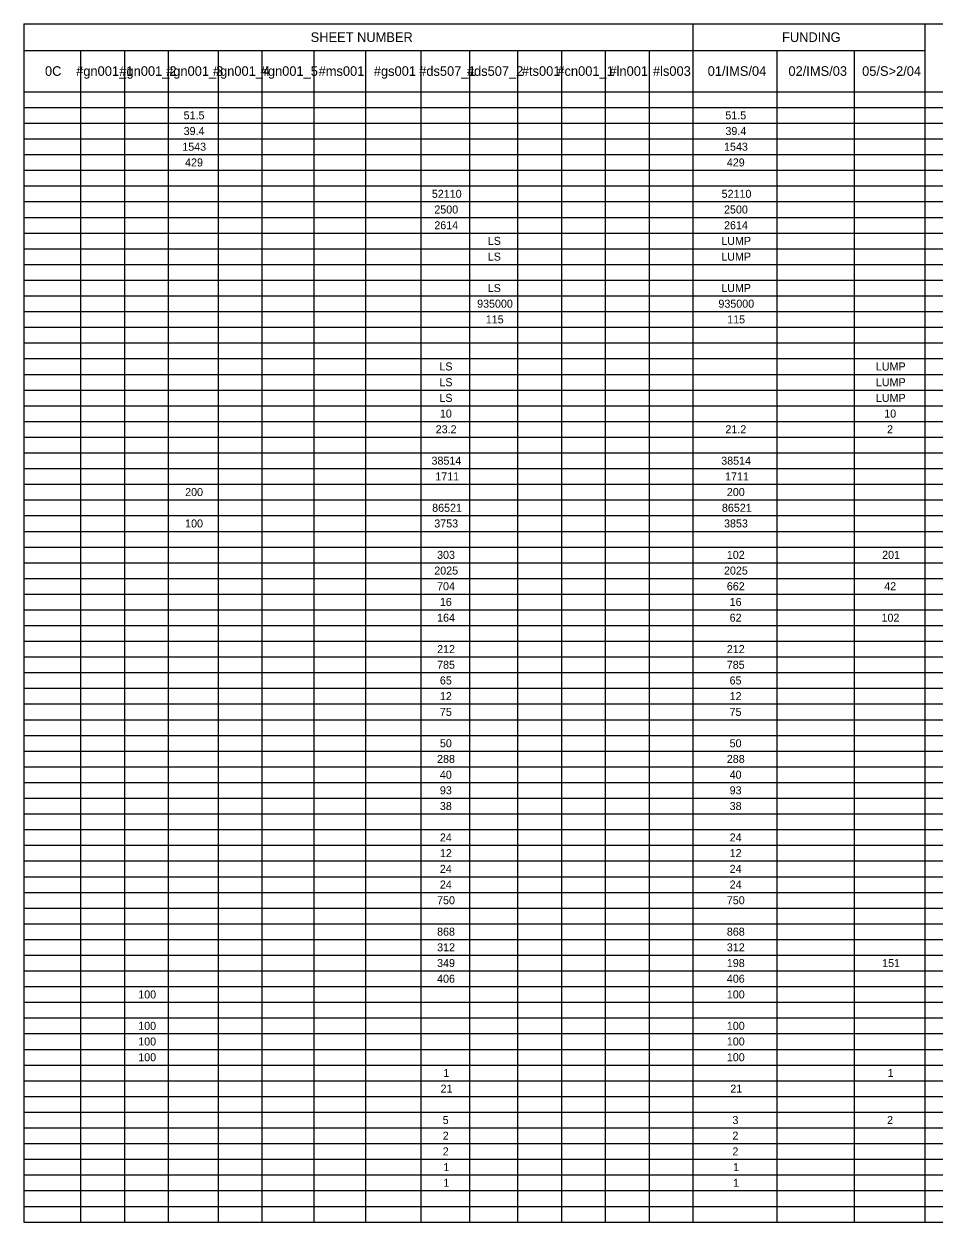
# Model space of a CAD drawing. Extents: x -542 to 295, y -281 to 32.
# Drawn here: x -541.71 to -525.79, y -40.54 to -19.59 of the extents above; entities that cross this region are included whole.
import ezdxf

# ---------------------------------------------------------------- set-up
doc = ezdxf.new("R2010")
doc.units = 0
doc.layers.add('SH_Data', color=7, linetype='Continuous')
doc.layers.add('SH_Text', color=7, linetype='Continuous')

msp = doc.modelspace()

# ---------------------------------------------------------------- linework, layer by layer
at = {"layer": 'SH_Data'}
for p, q in [((-541.706, -19.593), (-511.206, -19.593)), ((-541.706, -19.593), (-541.706, -40.543)), ((-530.01, -19.593), (-530.01, -40.543)), ((-525.956, -19.593), (-525.956, -40.543)), ((-541.706, -20.054), (-525.956, -20.054)), ((-540.716, -20.054), (-540.716, -40.543)), ((-539.95, -20.054), (-539.95, -40.543)), ((-539.184, -20.054), (-539.184, -40.543)), ((-538.311, -20.054), (-538.311, -40.543)), ((-537.545, -20.054), (-537.545, -40.543)), ((-536.64, -20.054), (-536.64, -40.543)), ((-535.736, -20.054), (-535.736, -40.543)), ((-534.767, -20.054), (-534.767, -40.543)), ((-533.916, -20.054), (-533.916, -40.543)), ((-533.075, -20.054), (-533.075, -40.543)), ((-532.309, -20.054), (-532.309, -40.543)), ((-531.543, -20.054), (-531.543, -40.543)), ((-530.776, -20.054), (-530.776, -40.543)), ((-528.542, -20.054), (-528.542, -40.543)), ((-527.19, -20.054), (-527.19, -40.543)), ((-541.706, -20.778), (-511.206, -20.778)), ((-541.706, -21.053), (-511.206, -21.053)), ((-541.706, -21.327), (-511.206, -21.327)), ((-541.706, -21.602), (-511.206, -21.602)), ((-541.706, -21.876), (-511.206, -21.876)), ((-541.706, -22.151), (-511.206, -22.151)), ((-541.706, -22.425), (-511.206, -22.425)), ((-541.706, -22.7), (-511.206, -22.7)), ((-541.706, -22.975), (-511.206, -22.975)), ((-541.706, -23.249), (-511.206, -23.249)), ((-541.706, -23.524), (-511.206, -23.524)), ((-541.706, -23.798), (-511.206, -23.798)), ((-541.706, -24.073), (-511.206, -24.073)), ((-541.706, -24.347), (-511.206, -24.347)), ((-541.706, -24.622), (-511.206, -24.622)), ((-541.706, -24.896), (-511.206, -24.896)), ((-541.706, -25.171), (-511.206, -25.171)), ((-541.706, -25.445), (-511.206, -25.445)), ((-541.706, -25.72), (-511.206, -25.72)), ((-541.706, -25.994), (-511.206, -25.994)), ((-541.706, -26.269), (-511.206, -26.269)), ((-541.706, -26.543), (-511.206, -26.543)), ((-541.706, -26.818), (-511.206, -26.818)), ((-541.706, -27.092), (-511.206, -27.092)), ((-541.706, -27.367), (-511.206, -27.367)), ((-541.706, -27.641), (-511.206, -27.641)), ((-541.706, -27.916), (-511.206, -27.916)), ((-541.706, -28.19), (-511.206, -28.19)), ((-541.706, -28.465), (-511.206, -28.465)), ((-541.706, -28.739), (-511.206, -28.739)), ((-541.706, -29.014), (-511.206, -29.014)), ((-541.706, -29.288), (-511.206, -29.288)), ((-541.706, -29.563), (-511.206, -29.563)), ((-541.706, -29.837), (-511.206, -29.837)), ((-541.706, -30.112), (-511.206, -30.112)), ((-541.706, -30.386), (-511.206, -30.386)), ((-541.706, -30.661), (-511.206, -30.661)), ((-541.706, -30.935), (-511.206, -30.935)), ((-541.706, -31.21), (-511.206, -31.21)), ((-541.706, -31.484), (-511.206, -31.484)), ((-541.706, -31.759), (-511.206, -31.759)), ((-541.706, -32.033), (-511.206, -32.033)), ((-541.706, -32.308), (-511.206, -32.308)), ((-541.706, -32.582), (-511.206, -32.582)), ((-541.706, -32.857), (-511.206, -32.857)), ((-541.706, -33.131), (-511.206, -33.131)), ((-541.706, -33.406), (-511.206, -33.406)), ((-541.706, -33.68), (-511.206, -33.68)), ((-541.706, -33.955), (-511.206, -33.955)), ((-541.706, -34.229), (-511.206, -34.229)), ((-541.706, -34.504), (-511.206, -34.504)), ((-541.706, -34.778), (-511.206, -34.778)), ((-541.706, -35.053), (-511.206, -35.053)), ((-541.706, -35.327), (-511.206, -35.327)), ((-541.706, -35.602), (-511.206, -35.602)), ((-541.706, -35.876), (-511.206, -35.876)), ((-541.706, -36.151), (-511.206, -36.151)), ((-541.706, -36.425), (-511.206, -36.425)), ((-541.706, -36.7), (-511.206, -36.7)), ((-541.706, -36.975), (-511.206, -36.975)), ((-541.706, -37.249), (-511.206, -37.249)), ((-541.706, -37.524), (-511.206, -37.524)), ((-541.706, -37.798), (-511.206, -37.798)), ((-541.706, -38.073), (-511.206, -38.073)), ((-541.706, -38.347), (-511.206, -38.347)), ((-541.706, -38.622), (-511.206, -38.622)), ((-541.706, -38.896), (-511.206, -38.896)), ((-541.706, -39.171), (-511.206, -39.171)), ((-541.706, -39.445), (-511.206, -39.445)), ((-541.706, -39.72), (-511.206, -39.72)), ((-541.706, -39.994), (-511.206, -39.994)), ((-541.706, -40.269), (-511.206, -40.269)), ((-541.706, -40.543), (-511.206, -40.543))]:
    msp.add_line(p, q, dxfattribs=at)

# ---------------------------------------------------------------- texts
at = {"layer": 'SH_Text'}
for s, height, p in [('SHEET NUMBER', 0.168, (-536.693, -19.907)), ('FUNDING', 0.168, (-528.452, -19.907)), ('0C', 0.168, (-541.338, -20.5)), ('#gn001_1', 0.168, (-540.793, -20.5)), ('#gn001_2', 0.168, (-540.038, -20.5)), ('#gn001_3', 0.168, (-539.22, -20.5)), ('#gn001_4', 0.168, (-538.402, -20.5)), ('#gn001_5', 0.168, (-537.566, -20.5)), ('#ms001', 0.168, (-536.554, -20.5)), ('#gs001', 0.168, (-535.589, -20.5)), ('#ds507_1', 0.168, (-534.796, -20.5)), ('#ds507_2', 0.168, (-533.962, -20.5)), ('#ts001', 0.168, (-533.001, -20.5)), ('#cn001_1', 0.168, (-532.38, -20.5)), ('#ln001', 0.168, (-531.469, -20.5)), ('#ls003', 0.168, (-530.709, -20.5)), ('01/IMS/04', 0.168, (-529.752, -20.5)), ('02/IMS/03', 0.168, (-528.34, -20.5)), ('05/S>2/04', 0.168, (-527.052, -20.5)), ('51.5', 0.14, (-538.914, -21.26)), ('51.5', 0.14, (-529.443, -21.26)), ('39.4', 0.14, (-538.914, -21.535)), ('39.4', 0.14, (-529.442, -21.535)), ('1543', 0.14, (-538.938, -21.809)), ('1543', 0.14, (-529.466, -21.809)), ('429', 0.14, (-538.889, -22.084)), ('429', 0.14, (-529.417, -22.084)), ('52110', 0.14, (-534.574, -22.633)), ('52110', 0.14, (-529.508, -22.633)), ('2500', 0.14, (-534.531, -22.907)), ('2500', 0.14, (-529.466, -22.907)), ('2614', 0.14, (-534.531, -23.182)), ('2614', 0.14, (-529.466, -23.182)), ('LS', 0.14, (-533.597, -23.456)), ('LUMP', 0.14, (-529.514, -23.456)), ('LS', 0.14, (-533.597, -23.731)), ('LUMP', 0.14, (-529.514, -23.731)), ('LS', 0.14, (-533.597, -24.28)), ('LUMP', 0.14, (-529.514, -24.28)), ('935000', 0.14, (-533.783, -24.554)), ('935000', 0.14, (-529.564, -24.554)), ('115', 0.14, (-533.631, -24.829)), ('115', 0.14, (-529.411, -24.829)), ('LS', 0.14, (-534.443, -25.652)), ('LUMP', 0.14, (-526.811, -25.652)), ('LS', 0.14, (-534.443, -25.927)), ('LUMP', 0.14, (-526.811, -25.927)), ('LS', 0.14, (-534.443, -26.201)), ('LUMP', 0.14, (-526.811, -26.201)), ('10', 0.14, (-534.434, -26.476)), ('10', 0.14, (-526.665, -26.476)), ('23.2', 0.14, (-534.507, -26.75)), ('21.2', 0.14, (-529.442, -26.75)), ('2', 0.14, (-526.616, -26.75)), ('38514', 0.14, (-534.58, -27.299)), ('38514', 0.14, (-529.515, -27.299)), ('1711', 0.14, (-534.514, -27.574)), ('1711', 0.14, (-529.448, -27.574)), ('200', 0.14, (-538.888, -27.848)), ('200', 0.14, (-529.417, -27.848)), ('86521', 0.14, (-534.569, -28.123)), ('86521', 0.14, (-529.503, -28.123)), ('100', 0.14, (-538.888, -28.397)), ('3753', 0.14, (-534.532, -28.397)), ('3853', 0.14, (-529.466, -28.397)), ('303', 0.14, (-534.483, -28.946)), ('102', 0.14, (-529.417, -28.946)), ('201', 0.14, (-526.702, -28.946)), ('2025', 0.14, (-534.532, -29.221)), ('2025', 0.14, (-529.467, -29.221)), ('704', 0.14, (-534.483, -29.495)), ('662', 0.14, (-529.417, -29.495)), ('42', 0.14, (-526.665, -29.495)), ('16', 0.14, (-534.434, -29.77)), ('16', 0.14, (-529.368, -29.77)), ('164', 0.14, (-534.483, -30.045)), ('62', 0.14, (-529.368, -30.045)), ('102', 0.14, (-526.713, -30.045)), ('212', 0.14, (-534.482, -30.594)), ('212', 0.14, (-529.417, -30.594)), ('785', 0.14, (-534.483, -30.868)), ('785', 0.14, (-529.418, -30.868)), ('65', 0.14, (-534.434, -31.143)), ('65', 0.14, (-529.369, -31.143)), ('12', 0.14, (-534.433, -31.417)), ('12', 0.14, (-529.368, -31.417)), ('75', 0.14, (-534.434, -31.692)), ('75', 0.14, (-529.369, -31.692)), ('50', 0.14, (-534.434, -32.241)), ('50', 0.14, (-529.368, -32.241)), ('288', 0.14, (-534.483, -32.515)), ('288', 0.14, (-529.417, -32.515)), ('40', 0.14, (-534.434, -32.79)), ('40', 0.14, (-529.368, -32.79)), ('93', 0.14, (-534.434, -33.064)), ('93', 0.14, (-529.368, -33.064)), ('38', 0.14, (-534.434, -33.339)), ('38', 0.14, (-529.368, -33.339)), ('24', 0.14, (-534.434, -33.888)), ('24', 0.14, (-529.368, -33.888)), ('12', 0.14, (-534.433, -34.162)), ('12', 0.14, (-529.368, -34.162)), ('24', 0.14, (-534.434, -34.437)), ('24', 0.14, (-529.368, -34.437)), ('24', 0.14, (-534.434, -34.711)), ('24', 0.14, (-529.368, -34.711)), ('750', 0.14, (-534.483, -34.986)), ('750', 0.14, (-529.417, -34.986)), ('868', 0.14, (-534.483, -35.535)), ('868', 0.14, (-529.417, -35.535)), ('312', 0.14, (-534.482, -35.809)), ('312', 0.14, (-529.417, -35.809)), ('349', 0.14, (-534.483, -36.084)), ('198', 0.14, (-529.417, -36.084)), ('151', 0.14, (-526.702, -36.084)), ('406', 0.14, (-534.483, -36.358)), ('406', 0.14, (-529.417, -36.358)), ('100', 0.14, (-539.708, -36.633)), ('100', 0.14, (-529.417, -36.633)), ('100', 0.14, (-539.708, -37.182)), ('100', 0.14, (-529.417, -37.182)), ('100', 0.14, (-539.708, -37.456)), ('100', 0.14, (-529.417, -37.456)), ('100', 0.14, (-539.708, -37.731)), ('100', 0.14, (-529.417, -37.731)), ('1', 0.14, (-534.373, -38.005)), ('1', 0.14, (-526.605, -38.005)), ('21', 0.14, (-534.422, -38.28)), ('21', 0.14, (-529.356, -38.28)), ('5', 0.14, (-534.385, -38.829)), ('3', 0.14, (-529.319, -38.829)), ('2', 0.14, (-526.616, -38.829)), ('2', 0.14, (-534.384, -39.103)), ('2', 0.14, (-529.319, -39.103)), ('2', 0.14, (-534.384, -39.378)), ('2', 0.14, (-529.319, -39.378)), ('1', 0.14, (-534.373, -39.652)), ('1', 0.14, (-529.308, -39.652)), ('1', 0.14, (-534.373, -39.927)), ('1', 0.14, (-529.308, -39.927))]:
    msp.add_text(s, height=height, dxfattribs=at).set_placement(p)

doc.saveas('drawing.dxf')
